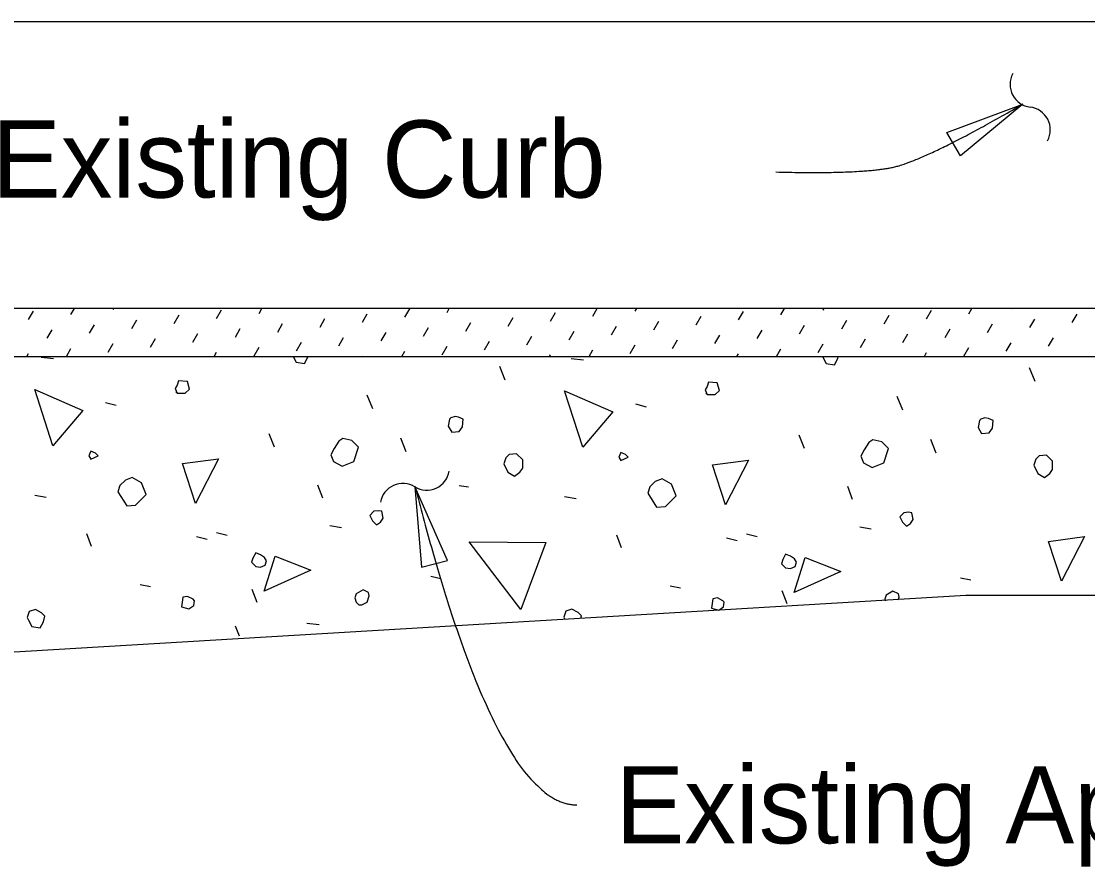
# Model space of a CAD drawing. Extents: x 21587 to 21656.3, y 56114 to 56157.2.
# Drawn here: x 21616.36 to 21619.146, y 56132.593 to 56134.801 of the extents above; entities that cross this region are included whole.
import ezdxf

# ---------------------------------------------------------------- set-up
doc = ezdxf.new("R2010")
doc.units = 0
for name, color, linetype in [('AdhocPoint_dp', 7, 'Continuous'), ('PlotBorder_dp', 7, 'Continuous'), ('SheetBorder_dp', 7, 'Continuous'), ('TextMisc', 7, 'Continuous')]:
    doc.layers.add(name, color=color, linetype=linetype)

msp = doc.modelspace()

# ---------------------------------------------------------------- linework, layer by layer
at = {"layer": 'AdhocPoint_dp'}
for p, q in [((21613.608, 56134.8009), (21621.5551, 56134.8009)), ((21624.3563, 56134.0511), (21613.608, 56134.0511)), ((21613.608, 56133.926), (21621.9231, 56133.926)), ((21618.8279, 56133.301), (21614.608, 56133.0509)), ((21624.3563, 56133.301), (21618.8279, 56133.301))]:
    msp.add_line(p, q, dxfattribs=at)
at = {"layer": 'PlotBorder_dp'}
for points in [[(21618.9767, 56134.5845), (21618.814, 56134.4497), (21618.7787, 56134.5108)], [(21617.3888, 56133.5857), (21617.4059, 56133.3752), (21617.4742, 56133.3926)]]:
    msp.add_lwpolyline(points, close=True, dxfattribs=at)
for centre, start, end in [((21619.0033, 56134.636), 151.5267, 263.2539), ((21618.9893, 56134.5176), 331.5267, 83.2539), ((21617.4197, 56133.6363), 238.4384, 350.1656), ((21617.3573, 56133.5347), 58.4384, 170.1656)]:
    msp.add_arc(centre, 0.0596, start, end, dxfattribs=at)
for points in [[(21618.3321, 56134.4076), (21618.5489, 56134.4019), (21618.72, 56134.4362), (21618.9767, 56134.5845)], [(21617.3892, 56133.5857), (21617.6004, 56132.7545), (21617.8116, 56132.7545)]]:
    msp.add_open_spline(points, degree=2, dxfattribs=at)
at = {"layer": 'TextMisc'}
for p, q in [((21616.3793, 56134.0219), (21616.3922, 56134.0443)), ((21616.4899, 56134.0349), (21616.4993, 56134.0511)), ((21616.6005, 56134.0479), (21616.6024, 56134.0511)), ((21616.76, 56134.012), (21616.773, 56134.0344)), ((21616.8706, 56134.0249), (21616.8836, 56134.0473)), ((21616.9813, 56134.0379), (21616.9889, 56134.0511)), ((21617.0919, 56134.0509), (21617.092, 56134.0511)), ((21617.2514, 56134.015), (21617.2643, 56134.0374)), ((21617.362, 56134.028), (21617.375, 56134.0504)), ((21617.4726, 56134.0409), (21617.4785, 56134.0511)), ((21617.7427, 56134.018), (21617.7557, 56134.0404)), ((21617.8534, 56134.031), (21617.865, 56134.0511)), ((21617.964, 56134.044), (21617.9681, 56134.0511)), ((21618.2341, 56134.021), (21618.2471, 56134.0434)), ((21618.3447, 56134.034), (21618.3546, 56134.0511)), ((21618.4554, 56134.047), (21618.4578, 56134.0511)), ((21618.7255, 56134.0241), (21618.7384, 56134.0465)), ((21618.8361, 56134.037), (21618.8442, 56134.0511)), ((21618.9467, 56134.05), (21618.9474, 56134.0511)), ((21619.1062, 56134.0141), (21619.1192, 56134.0365)), ((21616.5387, 56133.9861), (21616.5517, 56134.0084)), ((21616.6494, 56133.999), (21616.6623, 56134.0214)), ((21617.0301, 56133.9891), (21617.0431, 56134.0115)), ((21617.1407, 56134.002), (21617.1537, 56134.0244)), ((21617.5215, 56133.9921), (21617.5344, 56134.0145)), ((21617.6321, 56134.0051), (21617.6451, 56134.0275)), ((21618.0128, 56133.9951), (21618.0258, 56134.0175)), ((21618.1235, 56134.0081), (21618.1364, 56134.0305)), ((21618.3936, 56133.9852), (21618.4065, 56134.0076)), ((21618.5042, 56133.9981), (21618.5172, 56134.0205)), ((21618.6148, 56134.0111), (21618.6278, 56134.0335)), ((21618.8849, 56133.9882), (21618.8979, 56134.0106)), ((21618.9956, 56134.0012), (21619.0085, 56134.0235)), ((21616.4281, 56133.9731), (21616.4411, 56133.9955)), ((21616.8088, 56133.9631), (21616.8218, 56133.9855)), ((21616.9195, 56133.9761), (21616.9324, 56133.9985)), ((21617.3002, 56133.9662), (21617.3132, 56133.9886)), ((21617.4108, 56133.9791), (21617.4238, 56134.0015)), ((21617.6809, 56133.9562), (21617.6939, 56133.9786)), ((21617.7916, 56133.9692), (21617.8045, 56133.9916)), ((21617.9022, 56133.9822), (21617.9152, 56134.0045)), ((21618.1723, 56133.9592), (21618.1853, 56133.9816)), ((21618.2829, 56133.9722), (21618.2959, 56133.9946)), ((21618.6637, 56133.9623), (21618.6766, 56133.9847)), ((21618.7743, 56133.9752), (21618.7873, 56133.9976)), ((21616.5876, 56133.9372), (21616.6005, 56133.9596)), ((21616.6982, 56133.9502), (21616.7112, 56133.9726)), ((21617.0789, 56133.9402), (21617.0919, 56133.9626)), ((21617.1896, 56133.9532), (21617.2025, 56133.9756)), ((21617.4597, 56133.9303), (21617.4726, 56133.9527)), ((21617.5703, 56133.9433), (21617.5833, 56133.9657)), ((21617.951, 56133.9333), (21617.964, 56133.9557)), ((21618.0617, 56133.9463), (21618.0746, 56133.9687)), ((21618.4424, 56133.9363), (21618.4554, 56133.9587)), ((21618.553, 56133.9493), (21618.566, 56133.9717)), ((21618.9338, 56133.9394), (21618.9467, 56133.9617)), ((21619.0444, 56133.9523), (21619.0574, 56133.9747)), ((21616.3748, 56133.926), (21616.3793, 56133.9337)), ((21616.4123, 56133.9236), (21616.4441, 56133.9201)), ((21616.478, 56133.926), (21616.4899, 56133.9466)), ((21616.8645, 56133.926), (21616.8706, 56133.9367)), ((21616.9683, 56133.9273), (21616.9813, 56133.9497)), ((21617.2509, 56133.926), (21617.2514, 56133.9268)), ((21617.3541, 56133.926), (21617.362, 56133.9397)), ((21617.7406, 56133.926), (21617.7427, 56133.9298)), ((21617.8437, 56133.926), (21617.8534, 56133.9427)), ((21618.2302, 56133.926), (21618.2341, 56133.9328)), ((21618.3333, 56133.926), (21618.3447, 56133.9458)), ((21618.7198, 56133.926), (21618.7255, 56133.9358)), ((21618.8231, 56133.9264), (21618.8361, 56133.9488)), ((21617.6243, 56133.8641), (21617.6102, 56133.8995)), ((21617.7969, 56133.9201), (21617.8288, 56133.9165)), ((21619.009, 56133.8606), (21618.9949, 56133.8959)), ((21617.2785, 56133.7892), (21617.2643, 56133.8246)), ((21618.6631, 56133.7857), (21618.649, 56133.8211)), ((21616.5802, 56133.8051), (21616.6085, 56133.7981)), ((21617.9649, 56133.8016), (21617.9932, 56133.7945)), ((21617.0221, 56133.6885), (21617.008, 56133.7238)), ((21617.3662, 56133.6767), (21617.3521, 56133.7121)), ((21618.4068, 56133.6849), (21618.3927, 56133.7203)), ((21618.7509, 56133.6732), (21618.7368, 56133.7085)), ((21617.1477, 56133.5559), (21617.1353, 56133.5895)), ((21617.5041, 56133.5883), (21617.5289, 56133.5848)), ((21616.3952, 56133.5636), (21616.4253, 56133.5583)), ((21618.5323, 56133.5524), (21618.52, 56133.5859)), ((21617.7799, 56133.5601), (21617.8099, 56133.5547)), ((21617.1665, 56133.484), (21617.1965, 56133.4787)), ((21618.5512, 56133.4805), (21618.5812, 56133.4752)), ((21616.5437, 56133.4292), (21616.5313, 56133.4628)), ((21616.8177, 56133.4558), (21616.846, 56133.4487)), ((21616.8701, 56133.4657), (21616.8984, 56133.4587)), ((21617.9284, 56133.4257), (21617.916, 56133.4593)), ((21618.2024, 56133.4522), (21618.2307, 56133.4451)), ((21618.2548, 56133.4622), (21618.2831, 56133.4551)), ((21617.4299, 56133.3515), (21617.4564, 56133.3462)), ((21618.8145, 56133.3479), (21618.8411, 56133.3426)), ((21616.671, 56133.3302), (21616.6975, 56133.3249)), ((21616.9762, 56133.2831), (21616.9638, 56133.3167)), ((21618.0557, 56133.3267), (21618.0822, 56133.3214)), ((21618.3609, 56133.2796), (21618.3485, 56133.3132)), ((21617.1064, 56133.2295), (21617.1382, 56133.2259)), ((21616.9302, 56133.1952), (21616.9196, 56133.2217))]:
    msp.add_line(p, q, dxfattribs=at)
for points in [[(21617.0705, 56133.926), (21617.0787, 56133.9112), (21617.0999, 56133.9077), (21617.1088, 56133.9236), (21617.1094, 56133.926)], [(21618.4533, 56133.926), (21618.4545, 56133.9236)], [(21618.4545, 56133.9236), (21618.4634, 56133.9077), (21618.4846, 56133.9041), (21618.4934, 56133.9201), (21618.4949, 56133.926)], [(21616.4429, 56133.6926), (21616.3952, 56133.8394), (21616.5207, 56133.7846), (21616.4429, 56133.6926)], [(21616.7676, 56133.8299), (21616.7888, 56133.8299), (21616.7994, 56133.8405), (21616.7941, 56133.8599), (21616.7711, 56133.8617), (21616.7676, 56133.8511), (21616.7623, 56133.8423), (21616.7676, 56133.8299), (21616.764, 56133.8334)], [(21618.1523, 56133.8264), (21618.1735, 56133.8264), (21618.1841, 56133.837), (21618.1788, 56133.8564), (21618.1558, 56133.8582), (21618.1523, 56133.8476), (21618.147, 56133.8387), (21618.1523, 56133.8264), (21618.1487, 56133.8299)], [(21617.8276, 56133.6891), (21617.7799, 56133.8358), (21617.9054, 56133.781), (21617.8276, 56133.6891)], [(21617.4758, 56133.7439), (21617.4847, 56133.728), (21617.5041, 56133.7298), (21617.513, 56133.7421), (21617.5147, 56133.7616), (21617.5023, 56133.7669), (21617.4935, 56133.7686), (21617.4829, 56133.7651), (21617.4794, 56133.7616), (21617.4758, 56133.7439)], [(21618.8605, 56133.7404), (21618.8693, 56133.7245), (21618.8888, 56133.7262), (21618.8976, 56133.7386), (21618.8994, 56133.758), (21618.887, 56133.7633), (21618.8782, 56133.7651), (21618.8676, 56133.7616), (21618.864, 56133.758), (21618.8605, 56133.7404)], [(21617.1759, 56133.6514), (21617.1989, 56133.639), (21617.229, 56133.6514), (21617.2413, 56133.6885), (21617.2237, 56133.7062), (21617.2007, 56133.7115), (21617.1901, 56133.7044), (21617.1777, 56133.6849), (21617.1689, 56133.669), (21617.1759, 56133.6514)], [(21618.5606, 56133.6478), (21618.5836, 56133.6354), (21618.6136, 56133.6478), (21618.626, 56133.6849), (21618.6083, 56133.7026), (21618.5854, 56133.7079), (21618.5748, 56133.7008), (21618.5624, 56133.6814), (21618.5535, 56133.6655), (21618.5606, 56133.6478)], [(21616.5419, 56133.6573), (21616.5614, 56133.6661), (21616.5543, 56133.6732), (21616.5419, 56133.6785), (21616.5366, 56133.6661), (21616.5419, 56133.6573)], [(21617.9266, 56133.6537), (21617.9461, 56133.6626), (21617.939, 56133.6697), (21617.9266, 56133.675), (21617.9213, 56133.6626), (21617.9266, 56133.6537)], [(21616.8153, 56133.5417), (21616.7817, 56133.646), (21616.8754, 56133.6584), (21616.8153, 56133.5417)], [(21617.6208, 56133.6449), (21617.6314, 56133.6237), (21617.6491, 56133.6131), (21617.6632, 56133.6237), (21617.6703, 56133.6343), (21617.6703, 56133.6555), (21617.6544, 56133.6714), (21617.6349, 56133.6697), (21617.6261, 56133.6608), (21617.6208, 56133.6449)], [(21618.2, 56133.5382), (21618.1664, 56133.6425), (21618.2601, 56133.6549), (21618.2, 56133.5382)], [(21619.0055, 56133.6414), (21619.0161, 56133.6202), (21619.0338, 56133.6096), (21619.0479, 56133.6202), (21619.055, 56133.6308), (21619.055, 56133.652), (21619.0391, 56133.6679), (21619.0196, 56133.6661), (21619.0108, 56133.6573), (21619.0055, 56133.6414)], [(21616.6126, 56133.5724), (21616.6356, 56133.5353), (21616.6586, 56133.5371), (21616.6674, 56133.5459), (21616.6869, 56133.5654), (21616.6745, 56133.5954), (21616.6498, 56133.6096), (21616.6321, 56133.6025), (21616.6179, 56133.5883), (21616.6126, 56133.5724)], [(21617.9973, 56133.5689), (21618.0203, 56133.5318), (21618.0433, 56133.5335), (21618.0521, 56133.5424), (21618.0716, 56133.5618), (21618.0592, 56133.5919), (21618.0344, 56133.606), (21618.0168, 56133.5989), (21618.0026, 56133.5848), (21617.9973, 56133.5689)], [(21617.2778, 56133.4964), (21617.2884, 56133.4858), (21617.2991, 56133.4929), (21617.3061, 56133.5035), (21617.3026, 56133.5212), (21617.2938, 56133.5229), (21617.2814, 56133.5212), (21617.2708, 56133.5106), (21617.2778, 56133.4964)], [(21618.6625, 56133.4929), (21618.6731, 56133.4823), (21618.6837, 56133.4893), (21618.6908, 56133.4999), (21618.6873, 56133.5176), (21618.6784, 56133.5194), (21618.6661, 56133.5176), (21618.6554, 56133.507), (21618.6625, 56133.4929)], [(21619.0778, 56133.3385), (21619.0443, 56133.4428), (21619.1379, 56133.4551), (21619.0778, 56133.3385)], [(21617.665, 56133.2648), (21617.5306, 56133.4416), (21617.7304, 56133.4398), (21617.665, 56133.2648)], [(21616.9726, 56133.3773), (21616.985, 56133.3756), (21616.9974, 56133.3809), (21617.0009, 56133.3915), (21616.9956, 56133.4003), (21616.985, 56133.4074), (21616.9726, 56133.4127), (21616.9656, 56133.3986), (21616.962, 56133.388), (21616.9726, 56133.3773)], [(21616.995, 56133.3126), (21617.0233, 56133.4045), (21617.117, 56133.3674), (21616.995, 56133.3126)], [(21618.3573, 56133.3738), (21618.3697, 56133.372), (21618.3821, 56133.3773), (21618.3856, 56133.388), (21618.3803, 56133.3968), (21618.3697, 56133.4039), (21618.3573, 56133.4092), (21618.3503, 56133.395), (21618.3467, 56133.3844), (21618.3573, 56133.3738)], [(21618.3797, 56133.309), (21618.408, 56133.401), (21618.5017, 56133.3638), (21618.3797, 56133.309)], [(21617.2425, 56133.2772), (21617.2496, 56133.2772), (21617.2637, 56133.2843), (21617.269, 56133.3002), (21617.2672, 56133.309), (21617.2531, 56133.3161), (21617.2354, 56133.3055), (21617.2319, 56133.2949), (21617.2354, 56133.2843), (21617.2425, 56133.2772)], [(21618.6514, 56133.2899), (21618.6537, 56133.2967), (21618.6519, 56133.3055), (21618.6378, 56133.3126), (21618.6201, 56133.302), (21618.6166, 56133.2914), (21618.6177, 56133.2878)], [(21616.7788, 56133.2719), (21616.7983, 56133.2666), (21616.8106, 56133.2754), (21616.8124, 56133.2878), (21616.8089, 56133.2914), (21616.7947, 56133.2984), (21616.7824, 56133.2967), (21616.7806, 56133.2843), (21616.7788, 56133.2719)], [(21618.1635, 56133.2684), (21618.1829, 56133.2631), (21618.1953, 56133.2719), (21618.1971, 56133.2843), (21618.1935, 56133.2878), (21618.1794, 56133.2949), (21618.167, 56133.2931), (21618.1653, 56133.2807), (21618.1635, 56133.2684)], [(21616.3793, 56133.2366), (21616.3881, 56133.2206), (21616.4094, 56133.2171), (21616.4182, 56133.233), (21616.4217, 56133.2472), (21616.4129, 56133.256), (21616.397, 56133.2648), (21616.3811, 56133.2595), (21616.3758, 56133.2436), (21616.3793, 56133.2366)], [(21617.8221, 56133.2418), (21617.8237, 56133.2484), (21617.8149, 56133.2572), (21617.799, 56133.2661), (21617.7831, 56133.2608), (21617.7778, 56133.2449), (21617.7806, 56133.2392)]]:
    msp.add_lwpolyline(points, dxfattribs=at)

# ---------------------------------------------------------------- texts
at = {"layer": 'SheetBorder_dp'}
for s, p in [('Existing Curb', (21616.2837, 56134.3406)), ('Existing Approach Slab', (21617.9127, 56132.654))]:
    msp.add_text(s, height=0.2016, dxfattribs=at).set_placement(p)

doc.saveas('drawing.dxf')
